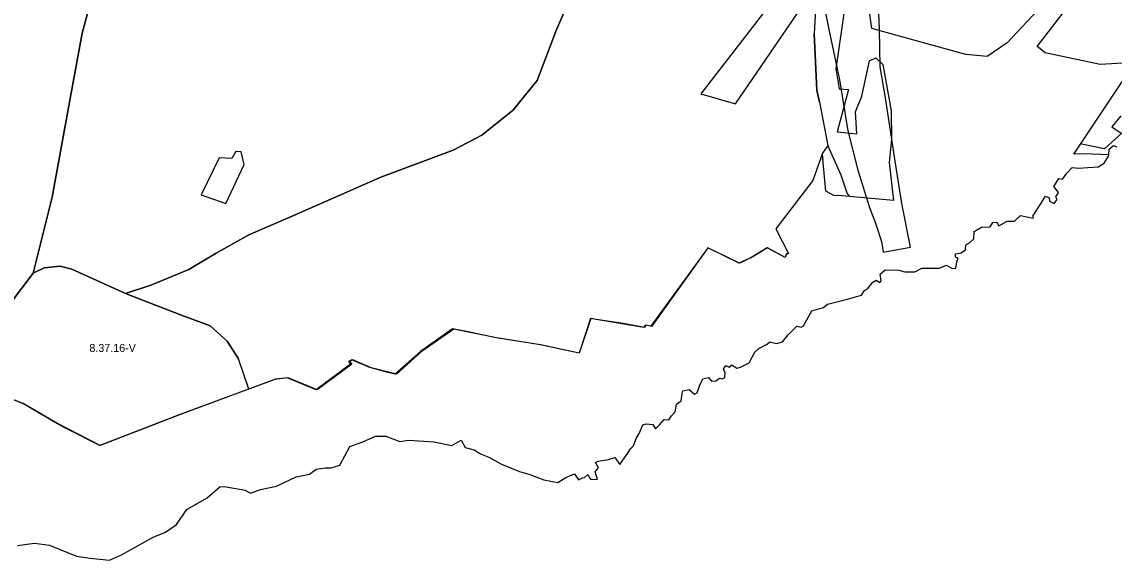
# Model space of a CAD drawing. Extents: x -547623 to -533936, y -1096714 to -1086523.
# Drawn here: x -542784 to -541420, y -1094788 to -1094116 of the extents above; entities that cross this region are included whole.
import ezdxf

# ---------------------------------------------------------------- set-up
doc = ezdxf.new("R2010")
doc.units = 0
for name, color, linetype in [('Vrstva 27', 7, 'Continuous'), ('Vrstva 28', 7, 'Continuous'), ('Vrstva 29', 7, 'Continuous')]:
    doc.layers.add(name, color=color, linetype=linetype)

msp = doc.modelspace()

# ---------------------------------------------------------------- linework, layer by layer
at = {"layer": 'Vrstva 28'}
for p, q in [((-542076, -1094032), (-542116.5, -1094126.5)), ((-542116.5, -1094126.5), (-542076, -1094032)), ((-542688.5, -1094055), (-542708.5, -1094129.5)), ((-542708.5, -1094129.5), (-542688.5, -1094055)), ((-541790.8, -1094068.4), (-541794.5, -1094130.5)), ((-542116.5, -1094126.5), (-542140.5, -1094189)), ((-542140.5, -1094189), (-542116.5, -1094126.5)), ((-542708.5, -1094129.5), (-542724.3, -1094215.9)), ((-542724.3, -1094215.9), (-542708.5, -1094129.5)), ((-541794.5, -1094130.5), (-541791, -1094201)), ((-541791, -1094201), (-541794.5, -1094130.5)), ((-541794.5, -1094130.5), (-541794.5, -1094130.5)), ((-542140.5, -1094189), (-542162.3, -1094215.9)), ((-542162.3, -1094215.9), (-542140.5, -1094189)), ((-541791, -1094201), (-541787.6, -1094215.9)), ((-541787.6, -1094215.9), (-541791, -1094201)), ((-542724.3, -1094215.9), (-542746, -1094334.5)), ((-542746, -1094334.5), (-542724.3, -1094215.9)), ((-542162.3, -1094215.9), (-542170, -1094225.5)), ((-542170, -1094225.5), (-542162.3, -1094215.9)), ((-541787.6, -1094215.9), (-541777.4, -1094269.9)), ((-542170, -1094225.5), (-542209.5, -1094257)), ((-542209.5, -1094257), (-542170, -1094225.5)), ((-542209.5, -1094257), (-542245.5, -1094276)), ((-542245.5, -1094276), (-542209.5, -1094257)), ((-542245.5, -1094276), (-542335.5, -1094309.5)), ((-542335.5, -1094309.5), (-542245.5, -1094276)), ((-541777.4, -1094269.9), (-541784.2, -1094279.4)), ((-541760.5, -1094307), (-541777.4, -1094269.9)), ((-542335.5, -1094309.5), (-542446.5, -1094358.5)), ((-542446.5, -1094358.5), (-542335.5, -1094309.5)), ((-541753, -1094329.5), (-541760.5, -1094307)), ((-541750.1, -1094333.4), (-541753, -1094329.5)), ((-542746, -1094334.5), (-542770, -1094429.5)), ((-542770, -1094429.5), (-542746, -1094334.5)), ((-542446.5, -1094358.5), (-542500.5, -1094381.5)), ((-542500.5, -1094381.5), (-542446.5, -1094358.5)), ((-542500.5, -1094381.5), (-542541.5, -1094404.5)), ((-542541.5, -1094404.5), (-542500.5, -1094381.5)), ((-542541.5, -1094404.5), (-542575.5, -1094425)), ((-542575.5, -1094425), (-542541.5, -1094404.5)), ((-542756, -1094423), (-542770, -1094429.5)), ((-542770, -1094429.5), (-542756, -1094423)), ((-542736, -1094421), (-542756, -1094423)), ((-542756, -1094423), (-542736, -1094421)), ((-542721.5, -1094424.5), (-542736, -1094421)), ((-542736, -1094421), (-542721.5, -1094424.5)), ((-542654.5, -1094455), (-542721.5, -1094424.5)), ((-542721.5, -1094424.5), (-542654.5, -1094455)), ((-542575.5, -1094425), (-542623, -1094444.5)), ((-542623, -1094444.5), (-542575.5, -1094425)), ((-542770, -1094429.5), (-542798, -1094467)), ((-542798, -1094467), (-542770, -1094429.5)), ((-542623, -1094444.5), (-542654.5, -1094455)), ((-542654.5, -1094455), (-542623, -1094444.5)), ((-542586, -1094481.5), (-542654.5, -1094455)), ((-542654.5, -1094455), (-542586, -1094481.5)), ((-542549, -1094495.5), (-542586, -1094481.5)), ((-542586, -1094481.5), (-542549, -1094495.5)), ((-542527.5, -1094514.5), (-542549, -1094495.5)), ((-542549, -1094495.5), (-542527.5, -1094514.5)), ((-542513.5, -1094536.5), (-542527.5, -1094514.5)), ((-542527.5, -1094514.5), (-542513.5, -1094536.5)), ((-542500.6, -1094574.7), (-542513.5, -1094536.5))]:
    msp.add_line(p, q, dxfattribs=at)
for points in [[(-542688.5, -1094055), (-542708.5, -1094129.5), (-542724.3, -1094215.9), (-542746, -1094334.5), (-542770, -1094429.5), (-542756, -1094423), (-542736, -1094421), (-542721.5, -1094424.5), (-542654.5, -1094455), (-542623, -1094444.5), (-542575.5, -1094425), (-542541.5, -1094404.5), (-542500.5, -1094381.5), (-542446.5, -1094358.5), (-542335.5, -1094309.5), (-542245.5, -1094276), (-542209.5, -1094257), (-542170, -1094225.5), (-542162.3, -1094215.9), (-542140.5, -1094189), (-542116.5, -1094126.5), (-542076, -1094032)], [(-541747.2, -1094036), (-541767.5, -1094174.4), (-541763, -1094199.3), (-541751.6, -1094200.2), (-541765.7, -1094252.8), (-541741.1, -1094255.6), (-541742.6, -1094228.1), (-541734.7, -1094208.4), (-541725.3, -1094164.4), (-541717.6, -1094160.4), (-541708.7, -1094168.7), (-541698.1, -1094226.6), (-541698, -1094262.7), (-541700.9, -1094291.2), (-541695.2, -1094338.6), (-541759.5, -1094332.9), (-541769.7, -1094332.6), (-541779.8, -1094327.2), (-541783.6, -1094286.6), (-541784, -1094288.1), (-541783.6, -1094286.6), (-541784.2, -1094279.4), (-541795.9, -1094313.9), (-541842.1, -1094374.3), (-541826.6, -1094404.8)], [(-541790.8, -1094068.4), (-541780.3, -1094053.1), (-541858.9, -1094105.9), (-541935.8, -1094205.5), (-541892.7, -1094217.8), (-541790.8, -1094068.4), (-541790.8, -1094068.4)], [(-541497.3, -1094081.4), (-541553.4, -1094141.9), (-541578.2, -1094158.8), (-541604.9, -1094156.3), (-541670, -1094138.6), (-541722.5, -1094123.8), (-541729.7, -1094070.2)], [(-541402.4, -1094166.8), (-541437.4, -1094168.9), (-541505.8, -1094154.1), (-541515.8, -1094146.5), (-541468, -1094083.7)], [(-541648.2, -1094423.1), (-541637.8, -1094423.2), (-541629.4, -1094419.7), (-541621.7, -1094423.9), (-541617.3, -1094423.3), (-541616.3, -1094415.5), (-541614.4, -1094411), (-541617.9, -1094409.7), (-541618, -1094405.2), (-541610.7, -1094404.1), (-541605.6, -1094400.4), (-541604.9, -1094394.3), (-541600.6, -1094391.8), (-541594.8, -1094386.5), (-541594.6, -1094377.6), (-541585.5, -1094372.2), (-541574.6, -1094371.7), (-541571.3, -1094366.4), (-541566.3, -1094365.9), (-541563.8, -1094370.3), (-541553.4, -1094364.4), (-541544.1, -1094364.4), (-541542.6, -1094363), (-541536.7, -1094357.6), (-541520.7, -1094361), (-541520.9, -1094357.7), (-541513.9, -1094346.5), (-541505.5, -1094333.3), (-541500.8, -1094335.3), (-541500.6, -1094339.4), (-541494.5, -1094342.6), (-541491.1, -1094337.3), (-541492.4, -1094334.1), (-541489.1, -1094328.6), (-541495.2, -1094321.4), (-541488.7, -1094311.1), (-541484.1, -1094311.9), (-541479, -1094304.4), (-541472.3, -1094297.4), (-541463.9, -1094298.3), (-541452.7, -1094297.4), (-541439.8, -1094296.8), (-541432.3, -1094292.1), (-541426.7, -1094283.4), (-541426.6, -1094281.8), (-541456.8, -1094280.6), (-541470, -1094280.7), (-541461.7, -1094268.2), (-541399.2, -1094174.8)], [(-541409.5, -1094253.8), (-541432, -1094274), (-541462.1, -1094268.1)], [(-542789.3, -1094769.8), (-542768.2, -1094766.8), (-542749.4, -1094769.5), (-542715.9, -1094783.3), (-542698.7, -1094785.5), (-542674.7, -1094788.2), (-542659.7, -1094781.6), (-542619.8, -1094759.5), (-542604.6, -1094753.2), (-542591, -1094743.7), (-542577.8, -1094724.7), (-542552.5, -1094710.2), (-542536.2, -1094696), (-542528.8, -1094696.6), (-542505.2, -1094700.8), (-542498.6, -1094704.4), (-542485.8, -1094699.8), (-542466, -1094695.6), (-542441.2, -1094684), (-542424.6, -1094680.8), (-542416.3, -1094674.5), (-542404.8, -1094672.7), (-542397.5, -1094673), (-542386.9, -1094669.3), (-542374.5, -1094646.2), (-542358.2, -1094640.2), (-542342.1, -1094633.3), (-542329.2, -1094633.2), (-542312.1, -1094639.8), (-542300.6, -1094638.3), (-542269.5, -1094640.3), (-542247, -1094644.9), (-542235.2, -1094638.1), (-542230.4, -1094647.4), (-542218.9, -1094650.2), (-542211.2, -1094655.4), (-542200.6, -1094659.3), (-542185, -1094668.2), (-542162.3, -1094677.2), (-542149.7, -1094681.3), (-542131.9, -1094688), (-542114.7, -1094691), (-542104.5, -1094684.8), (-542093.8, -1094680.2), (-542088.7, -1094687.9), (-542083.8, -1094685.3), (-542081.3, -1094684.7), (-542077, -1094681.1), (-542075.6, -1094684.6), (-542073.3, -1094687.2), (-542064.9, -1094687.1), (-542066.5, -1094681.9), (-542067.9, -1094677.6), (-542063.8, -1094672.9), (-542067.4, -1094666.2), (-542064.2, -1094664.5), (-542051.3, -1094662.4), (-542043.3, -1094659.9), (-542037, -1094668.6), (-542028.2, -1094656.2), (-542024, -1094649.2), (-542019.7, -1094644.4), (-542016.8, -1094636.1), (-542013.1, -1094630.1), (-542008.5, -1094618.9), (-542004.4, -1094618), (-541996, -1094618.6), (-541992.5, -1094624), (-541987.8, -1094619.1), (-541981.7, -1094612.6), (-541976.1, -1094613), (-541972.8, -1094607.9), (-541968.1, -1094603), (-541966.4, -1094593.4), (-541960.5, -1094589.2), (-541959.4, -1094580.1), (-541958.3, -1094576.7), (-541950.4, -1094575), (-541943.8, -1094580.7), (-541940.6, -1094579.2), (-541937.4, -1094569.3), (-541933.5, -1094561.4), (-541926.5, -1094560), (-541922.5, -1094564.6), (-541917.1, -1094564.2), (-541912.5, -1094560.6), (-541909, -1094561.7), (-541906.1, -1094559.9), (-541905.6, -1094553.9), (-541907.8, -1094549.7), (-541904.6, -1094544.8), (-541900.4, -1094546.9), (-541897.1, -1094544.2), (-541891.2, -1094548.2), (-541886.4, -1094547.2), (-541875.4, -1094541.5), (-541868.6, -1094528.1), (-541863.7, -1094523.8), (-541853.3, -1094518.3), (-541849.9, -1094515.2), (-541841.5, -1094517.4), (-541833.8, -1094515.2), (-541826.9, -1094506.6), (-541816.2, -1094495.8), (-541810.8, -1094497.1), (-541807.8, -1094495.3), (-541797.4, -1094476.6), (-541782.6, -1094472.5), (-541777.7, -1094468.4), (-541752.8, -1094462.2), (-541735.1, -1094456.9), (-541731.4, -1094451.4), (-541727.8, -1094449.2), (-541721.1, -1094441), (-541716.9, -1094438.1), (-541712.4, -1094441.4), (-541710.7, -1094439.3), (-541711.8, -1094430.8), (-541705.7, -1094425.4), (-541688.5, -1094425.9), (-541681.3, -1094427.9), (-541668.7, -1094427.7), (-541659.9, -1094423.1), (-541637.8, -1094423.2), (-541629.4, -1094419.7), (-541621.7, -1094423.9), (-541617.3, -1094423.3), (-541616.3, -1094415.5), (-541614.4, -1094411), (-541617.9, -1094409.7), (-541618, -1094405.2), (-541610.7, -1094404.1), (-541605.6, -1094400.4), (-541604.9, -1094394.3), (-541600.6, -1094391.8), (-541594.8, -1094386.5), (-541594.6, -1094377.6), (-541585.5, -1094372.2), (-541574.6, -1094371.7), (-541571.3, -1094366.4), (-541566.3, -1094365.9), (-541563.8, -1094370.3), (-541553.4, -1094364.4), (-541544.1, -1094364.4), (-541542.6, -1094363), (-541536.7, -1094357.6), (-541520.7, -1094361), (-541520.9, -1094357.7), (-541513.9, -1094346.5), (-541505.5, -1094333.3), (-541500.8, -1094335.3), (-541500.6, -1094339.4), (-541494.5, -1094342.6), (-541491.1, -1094337.3), (-541492.4, -1094334.1), (-541489.1, -1094328.6), (-541495.2, -1094321.4), (-541488.7, -1094311.1), (-541484.1, -1094311.9), (-541479, -1094304.4), (-541472.3, -1094297.4), (-541463.9, -1094298.3), (-541452.7, -1094297.4), (-541439.8, -1094296.8), (-541432.3, -1094292.1), (-541426.7, -1094283.4), (-541426.6, -1094281.8), (-541425.9, -1094274.8), (-541420.7, -1094270), (-541416.5, -1094271.6)], [(-542521.8, -1094286.3), (-542537.6, -1094285.3), (-542560, -1094331.8), (-542529.3, -1094342.3), (-542506.3, -1094293.8), (-542510.2, -1094278), (-542516.7, -1094277.7), (-542521.8, -1094286.3)], [(-541826.6, -1094404.8), (-541829, -1094406), (-541830.2, -1094408.9), (-541830.6, -1094409.9), (-541852.9, -1094397.8), (-541871.7, -1094409.7), (-541883.9, -1094414.9), (-541888.3, -1094417), (-541927.1, -1094397.9), (-541928, -1094399.1), (-541997.7, -1094496.2), (-542004.8, -1094494.6), (-542006.2, -1094497.5), (-542033.1, -1094492.6), (-542063.7, -1094487.7), (-542073.2, -1094486.1), (-542087.8, -1094529.6), (-542136.3, -1094519.2), (-542189.3, -1094510.9), (-542244.5, -1094499.4), (-542285.2, -1094527.8), (-542316.2, -1094555.9), (-542347.9, -1094547.8), (-542370.6, -1094538), (-542374.8, -1094540.1), (-542372, -1094543.1), (-542415.2, -1094575.2), (-542451.3, -1094560.2), (-542467.3, -1094562.2), (-542586.9, -1094606.7), (-542686.1, -1094645.1), (-542740.4, -1094617.1), (-542782.5, -1094592.6), (-542818.6, -1094578.5)], [(-541826.4, -1094404.4), (-541829.2, -1094405.7), (-541830.3, -1094408.9), (-541830.7, -1094409.8), (-541853, -1094397.7), (-541872.2, -1094409.7), (-541883.3, -1094414.8), (-541887.7, -1094416.9), (-541927.3, -1094397.9), (-541928.2, -1094399), (-541998.3, -1094495.9), (-542005.4, -1094494.4), (-542007, -1094497.5), (-542064.1, -1094487.7), (-542073.6, -1094486.1), (-542088.1, -1094529.4), (-542136.8, -1094519.1), (-542193.7, -1094509.9), (-542226.4, -1094503), (-542246, -1094499.3), (-542286.3, -1094527.5), (-542318.1, -1094555.7), (-542326.6, -1094553.7), (-542349.4, -1094547.6), (-542371.9, -1094538), (-542376.2, -1094540.1), (-542373.5, -1094543.2), (-542416.6, -1094575.2), (-542452.6, -1094560.3), (-542468.2, -1094562.3), (-542587.7, -1094606.7), (-542686.7, -1094645.1), (-542731.2, -1094622.2), (-542742.2, -1094616.1), (-542782.7, -1094592.4), (-542818.2, -1094578.6)]]:
    msp.add_lwpolyline(points, dxfattribs=at)
at = {"layer": 'Vrstva 29'}
for points in [[(-541790.2, -1094054.2), (-541776.4, -1094122.9), (-541762.6, -1094188), (-541752.3, -1094251.9), (-541739.9, -1094300.7), (-541725.3, -1094347.7), (-541717.8, -1094367.2), (-541710.2, -1094389.9), (-541708.2, -1094403.4), (-541674.1, -1094396.9), (-541685.1, -1094342.3), (-541693.3, -1094289.6), (-541705.4, -1094210.6), (-541712.1, -1094171.6), (-541713, -1094124.7), (-541714.3, -1094084.7)], [(-541411.4, -1094233), (-541422.7, -1094246.9), (-541409.9, -1094255.3)]]:
    msp.add_lwpolyline(points, dxfattribs=at)

# ---------------------------------------------------------------- texts
at = {"layer": 'Vrstva 27'}
msp.add_text('8.37.16-V', height=10, dxfattribs=at).set_placement((-542699.6, -1094528))

doc.saveas('drawing.dxf')
